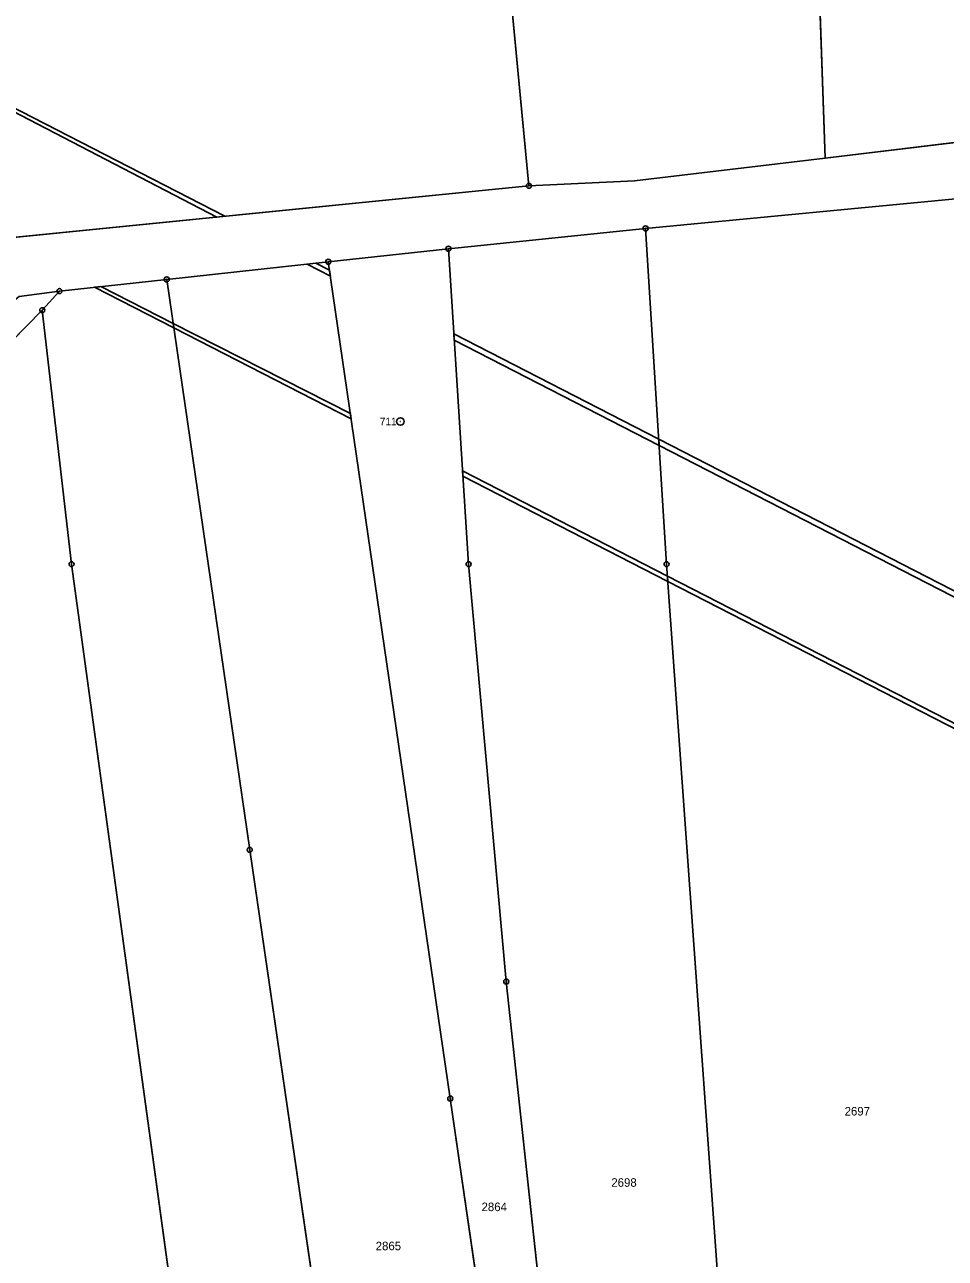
# Model space of a CAD drawing. Extents: x -689422 to -685210, y -987725 to -982160.
# Drawn here: x -688413.4 to -688229.9, y -985138.3 to -984892.5 of the extents above; entities that cross this region are included whole.
import ezdxf

# ---------------------------------------------------------------- set-up
doc = ezdxf.new("R2010")
doc.units = 0
for name, color, linetype in [('KN_Hranice_parcel', 7, 'Continuous'), ('KN_Parcelni cisla', 7, 'Continuous'), ('KN_Polygon parcely', 7, 'Continuous'), ('KN_POZEMKY_ORNA PUDA', 7, 'Continuous'), ('KN_POZEMKY_OSTATNI PLOCHA', 7, 'Continuous'), ('KN_VYUZITI_16_ostatni plocha_silnice', 7, 'Continuous'), ('KN_Věcná břemena k části', 7, 'Continuous'), ('KN_Značky bodu BP', 7, 'Continuous')]:
    doc.layers.add(name, color=color, linetype=linetype)

msp = doc.modelspace()

# ---------------------------------------------------------------- linework, layer by layer
at = {"layer": 'KN_Hranice_parcel'}
for p, q in [((-688216.8, -984914.64), (-688253.89, -984919.08)), ((-688312.89, -984924.62), (-688430.45, -984936.4)), ((-688289.65, -984933.1), (-688224.38, -984926.86)), ((-688328.94, -984937.15), (-688289.65, -984933.1)), ((-688352.86, -984939.75), (-688328.94, -984937.15)), ((-688385.06, -984943.26), (-688352.86, -984939.75)), ((-688406.43, -984945.6), (-688385.06, -984943.26)), ((-688414.48, -984946.69), (-688406.43, -984945.6)), ((-688409.85, -984949.4), (-688406.43, -984945.6))]:
    msp.add_line(p, q, dxfattribs=at)
for points in [[(-688313.92, -984691.95), (-688314.36, -984749.14), (-688315.14, -984804.5), (-688317.5, -984804.8), (-688317.25, -984879.1), (-688312.89, -984924.62)], [(-688249.21, -984716.85), (-688254.08, -984789.81), (-688255.52, -984871.05), (-688253.89, -984919.08)], [(-688253.89, -984919.08), (-688291.84, -984923.63), (-688312.89, -984924.62)], [(-688289.65, -984933.1), (-688285.47, -985000), (-688275.35, -985141.38), (-688261.8, -985217.11), (-688244.85, -985284.17), (-688237.3, -985310.26)], [(-688328.94, -984937.15), (-688324.91, -985000), (-688317.4, -985083.17), (-688308.47, -985166.13), (-688305.6, -985192.78), (-688296.5, -985240.18), (-688288, -985264.9), (-688275.45, -985300)], [(-688352.86, -984939.75), (-688328.56, -985106.49), (-688317.22, -985184.3), (-688299.9, -985303.19)], [(-688385.06, -984943.26), (-688368.51, -985056.91), (-688354.09, -985155.86), (-688342.75, -985233.72), (-688332.02, -985307.37)], [(-688505, -985036.88), (-688481.65, -985012.29), (-688468.54, -985000), (-688439.4, -984974.7), (-688422.86, -984962.6), (-688409.85, -984949.4)], [(-688409.85, -984949.4), (-688404.02, -985000), (-688382, -985160.82), (-688369.92, -985239.07), (-688353.35, -985310.15)]]:
    msp.add_lwpolyline(points, dxfattribs=at)
at = {"layer": 'KN_Polygon parcely'}
for points in [[(-688430.5, -984736.06), (-688458.41, -984747.35), (-688463.05, -984749.22), (-688460.11, -984784.83), (-688430.45, -984936.4), (-688312.89, -984924.62), (-688317.25, -984879.1), (-688317.5, -984804.8), (-688315.14, -984804.5), (-688314.36, -984749.14), (-688313.92, -984691.95), (-688343.07, -984688.32), (-688347.01, -984687.83), (-688358.53, -984688.95), (-688373.26, -984693.97), (-688386.37, -984701.91), (-688390.36, -984704.33), (-688410.52, -984717.05)], [(-688249.21, -984716.85), (-688256.4, -984714.25), (-688294.19, -984700.33), (-688313.92, -984691.95), (-688314.36, -984749.14), (-688315.14, -984804.5), (-688317.5, -984804.8), (-688317.25, -984879.1), (-688312.89, -984924.62), (-688291.84, -984923.63), (-688253.89, -984919.08), (-688255.52, -984871.05), (-688254.08, -984789.81)], [(-688222.68, -984730.24), (-688237.29, -984721.16), (-688249.21, -984716.85), (-688254.08, -984789.81), (-688255.52, -984871.05), (-688253.89, -984919.08), (-688216.8, -984914.64), (-688217.93, -984846.95), (-688213.55, -984744.81), (-688213.89, -984740.38)], [(-688261.8, -985217.11), (-688244.85, -985284.17), (-688237.3, -985310.26), (-688211.7, -985271.62), (-688196.65, -985227.45), (-688200.56, -985209.85), (-688210.79, -985155.72), (-688222.87, -985075.69), (-688224.93, -985025.03), (-688221.04, -985020.73), (-688224.38, -984926.86), (-688289.65, -984933.1), (-688285.47, -985000), (-688275.35, -985141.38)], [(-688305.6, -985192.78), (-688296.5, -985240.18), (-688288, -985264.9), (-688275.45, -985300), (-688259.58, -985342.52), (-688237.3, -985310.26), (-688244.85, -985284.17), (-688261.8, -985217.11), (-688275.35, -985141.38), (-688285.47, -985000), (-688289.65, -984933.1), (-688328.94, -984937.15), (-688324.91, -985000), (-688317.4, -985083.17), (-688308.47, -985166.13)], [(-688328.56, -985106.49), (-688317.22, -985184.3), (-688299.9, -985303.19), (-688275.45, -985300), (-688288, -985264.9), (-688296.5, -985240.18), (-688305.6, -985192.78), (-688308.47, -985166.13), (-688317.4, -985083.17), (-688324.91, -985000), (-688328.94, -984937.15), (-688352.86, -984939.75)], [(-688354.09, -985155.86), (-688342.75, -985233.72), (-688332.02, -985307.37), (-688299.9, -985303.19), (-688317.22, -985184.3), (-688328.56, -985106.49), (-688352.86, -984939.75), (-688385.06, -984943.26), (-688368.51, -985056.91)], [(-688369.92, -985239.07), (-688353.35, -985310.15), (-688350.9, -985309.83), (-688332.02, -985307.37), (-688342.75, -985233.72), (-688354.09, -985155.86), (-688368.51, -985056.91), (-688385.06, -984943.26), (-688406.43, -984945.6), (-688409.85, -984949.4), (-688404.02, -985000), (-688382, -985160.82)], [(-688481.65, -985012.29), (-688468.54, -985000), (-688439.4, -984974.7), (-688422.86, -984962.6), (-688409.85, -984949.4), (-688406.43, -984945.6), (-688414.48, -984946.69), (-688440.6, -984966.99), (-688481.98, -985003.75), (-688525.52, -985051.66), (-688567.21, -985092.87), (-688578.43, -985104.99), (-688584.83, -985110.3), (-688583.64, -985120.26), (-688574.77, -985111.39), (-688564.25, -985101.8), (-688524.58, -985061.02), (-688505, -985036.88)], [(-688508.2, -985135.28), (-688476.16, -985287.48), (-688468.2, -985325.3), (-688353.35, -985310.15), (-688369.92, -985239.07), (-688382, -985160.82), (-688404.02, -985000), (-688409.85, -984949.4), (-688422.86, -984962.6), (-688439.4, -984974.7), (-688468.54, -985000), (-688481.65, -985012.29), (-688505, -985036.88), (-688498.75, -985060.18), (-688485.45, -985128.16)]]:
    msp.add_lwpolyline(points, close=True, dxfattribs=at)
for points in [[(-687537.11, -985161.39), (-687577.48, -985139.1), (-687603.25, -985125.69), (-687627.5, -985112.99), (-687648.4, -985100.74), (-687668.87, -985090.37), (-687673.16, -985088.01), (-687693.37, -985076.9), (-687714.49, -985065.3), (-687742.77, -985049.76), (-687769.32, -985035.17), (-687793.86, -985021.69), (-687933.07, -984951.85), (-688045.75, -984923.73), (-688071.7, -984917.84), (-688109.1, -984909.36), (-688135.6, -984907.8), (-688175.71, -984910.94), (-688216.8, -984914.64), (-688253.89, -984919.08), (-688291.84, -984923.63), (-688312.89, -984924.62), (-688430.45, -984936.4)], [(-688414.48, -984946.69), (-688406.43, -984945.6), (-688385.06, -984943.26), (-688352.86, -984939.75), (-688328.94, -984937.15), (-688289.65, -984933.1), (-688224.38, -984926.86), (-688135.11, -984918.37), (-688111.99, -984919.35), (-688087.14, -984926.53), (-688075.18, -984929.83), (-688004.29, -984949.41), (-688003.44, -984949.58), (-687992, -984951.88), (-687951.09, -984960.09)]]:
    msp.add_lwpolyline(points, dxfattribs=at)
at = {"layer": 'KN_POZEMKY_ORNA PUDA'}
for p, q in [((-688255.52, -984871.05), (-688253.89, -984919.08)), ((-688253.89, -984919.08), (-688255.52, -984871.05)), ((-688312.89, -984924.62), (-688317.25, -984879.1)), ((-688317.25, -984879.1), (-688312.89, -984924.62)), ((-688216.8, -984914.64), (-688253.89, -984919.08)), ((-688253.89, -984919.08), (-688291.84, -984923.63)), ((-688312.89, -984924.62), (-688430.45, -984936.4)), ((-688291.84, -984923.63), (-688312.89, -984924.62)), ((-688289.65, -984933.1), (-688224.38, -984926.86)), ((-688328.94, -984937.15), (-688289.65, -984933.1)), ((-688289.65, -984933.1), (-688285.47, -985000)), ((-688285.47, -985000), (-688289.65, -984933.1)), ((-688352.86, -984939.75), (-688328.94, -984937.15)), ((-688324.91, -985000), (-688328.94, -984937.15)), ((-688328.94, -984937.15), (-688324.91, -985000)), ((-688385.06, -984943.26), (-688352.86, -984939.75)), ((-688328.56, -985106.49), (-688352.86, -984939.75)), ((-688352.86, -984939.75), (-688328.56, -985106.49)), ((-688406.43, -984945.6), (-688385.06, -984943.26)), ((-688368.51, -985056.91), (-688385.06, -984943.26)), ((-688385.06, -984943.26), (-688368.51, -985056.91)), ((-688414.48, -984946.69), (-688406.43, -984945.6)), ((-688406.43, -984945.6), (-688409.85, -984949.4)), ((-688409.85, -984949.4), (-688406.43, -984945.6)), ((-688422.86, -984962.6), (-688409.85, -984949.4)), ((-688409.85, -984949.4), (-688422.86, -984962.6)), ((-688409.85, -984949.4), (-688404.02, -985000)), ((-688404.02, -985000), (-688409.85, -984949.4)), ((-688404.02, -985000), (-688382, -985160.82)), ((-688382, -985160.82), (-688404.02, -985000)), ((-688317.4, -985083.17), (-688324.91, -985000)), ((-688324.91, -985000), (-688317.4, -985083.17)), ((-688285.47, -985000), (-688275.35, -985141.38)), ((-688275.35, -985141.38), (-688285.47, -985000)), ((-688354.09, -985155.86), (-688368.51, -985056.91)), ((-688368.51, -985056.91), (-688354.09, -985155.86)), ((-688308.47, -985166.13), (-688317.4, -985083.17)), ((-688317.4, -985083.17), (-688308.47, -985166.13)), ((-688317.22, -985184.3), (-688328.56, -985106.49)), ((-688328.56, -985106.49), (-688317.22, -985184.3))]:
    msp.add_line(p, q, dxfattribs=at)
at = {"layer": 'KN_POZEMKY_OSTATNI PLOCHA'}
for p, q in [((-688253.89, -984919.08), (-688216.8, -984914.64)), ((-688291.84, -984923.63), (-688253.89, -984919.08)), ((-688430.45, -984936.4), (-688312.89, -984924.62)), ((-688312.89, -984924.62), (-688291.84, -984923.63)), ((-688224.38, -984926.86), (-688289.65, -984933.1)), ((-688289.65, -984933.1), (-688328.94, -984937.15)), ((-688328.94, -984937.15), (-688352.86, -984939.75)), ((-688352.86, -984939.75), (-688385.06, -984943.26)), ((-688385.06, -984943.26), (-688406.43, -984945.6)), ((-688406.43, -984945.6), (-688414.48, -984946.69))]:
    msp.add_line(p, q, dxfattribs=at)
at = {"layer": 'KN_VYUZITI_16_ostatni plocha_silnice'}
for p, q in [((-688253.89, -984919.08), (-688216.8, -984914.64)), ((-688291.84, -984923.63), (-688253.89, -984919.08)), ((-688430.45, -984936.4), (-688312.89, -984924.62)), ((-688312.89, -984924.62), (-688291.84, -984923.63)), ((-688224.38, -984926.86), (-688289.65, -984933.1)), ((-688289.65, -984933.1), (-688328.94, -984937.15)), ((-688328.94, -984937.15), (-688352.86, -984939.75)), ((-688352.86, -984939.75), (-688385.06, -984943.26)), ((-688385.06, -984943.26), (-688406.43, -984945.6)), ((-688406.43, -984945.6), (-688414.48, -984946.69))]:
    msp.add_line(p, q, dxfattribs=at)
at = {"layer": 'KN_Věcná břemena k části'}
for points in [[(-688375.09, -984930.85), (-688373.5, -984930.69), (-688438.05, -984897.55), (-688437.92, -984898.25)], [(-688352.44, -984942.6), (-688352.62, -984941.41), (-688355.33, -984940.02), (-688357.06, -984940.21)], [(-688383.65, -984952.93), (-688383.78, -984952.02), (-688398.19, -984944.7), (-688399.43, -984944.83)], [(-688348.3, -984971.06), (-688348.45, -984969.99), (-688383.78, -984952.02), (-688383.65, -984952.93)], [(-688327.85, -984954.13), (-688327.77, -984955.39), (-688286.95, -984976.36), (-688287.03, -984975.09)], [(-688221.42, -985010), (-688221.47, -985008.75), (-688287.03, -984975.09), (-688286.95, -984976.36)], [(-688285.3, -985002.38), (-688326.1, -984981.43), (-688326.03, -984982.49), (-688285.22, -985003.45)], [(-688224.54, -985034.6), (-688224.58, -985033.55), (-688285.3, -985002.38), (-688285.22, -985003.45)]]:
    msp.add_lwpolyline(points, close=True, dxfattribs=at)
at = {"layer": 'KN_Značky bodu BP'}
for centre, radius in [((-688312.89, -984924.62), 0.5), ((-688312.89, -984924.62), 0.0303), ((-688289.65, -984933.1), 0.5), ((-688289.65, -984933.1), 0.0303), ((-688328.94, -984937.15), 0.5), ((-688352.86, -984939.75), 0.5), ((-688328.94, -984937.15), 0.0303), ((-688352.86, -984939.75), 0.0303), ((-688385.06, -984943.26), 0.5), ((-688385.06, -984943.26), 0.0303), ((-688406.43, -984945.6), 0.5), ((-688406.43, -984945.6), 0.0303), ((-688409.85, -984949.4), 0.5), ((-688409.85, -984949.4), 0.0303), ((-688338.5, -984971.58), 0.75), ((-688338.5, -984971.58), 0.03), ((-688404.02, -985000), 0.5), ((-688404.02, -985000), 0.0303), ((-688324.91, -985000), 0.5), ((-688324.91, -985000), 0.0303), ((-688285.47, -985000), 0.5), ((-688285.47, -985000), 0.0303), ((-688368.51, -985056.91), 0.5), ((-688368.51, -985056.91), 0.0303), ((-688317.4, -985083.17), 0.5), ((-688317.4, -985083.17), 0.0303), ((-688328.56, -985106.49), 0.5), ((-688328.56, -985106.49), 0.0303)]:
    msp.add_circle(centre, radius, dxfattribs=at)

# ---------------------------------------------------------------- texts
at = {"layer": 'KN_Parcelni cisla'}
for s, p in [('2697', (-688249.99, -985109.85)), ('2698', (-688296.47, -985124.05)), ('2864', (-688322.33, -985128.9)), ('2865', (-688343.42, -985136.69))]:
    msp.add_text(s, height=1.7, dxfattribs=at).set_placement(p)
at = {"layer": 'KN_Značky bodu BP'}
msp.add_text('711', height=1.5, dxfattribs=at).set_placement((-688342.6, -984972.33))

doc.saveas('drawing.dxf')
